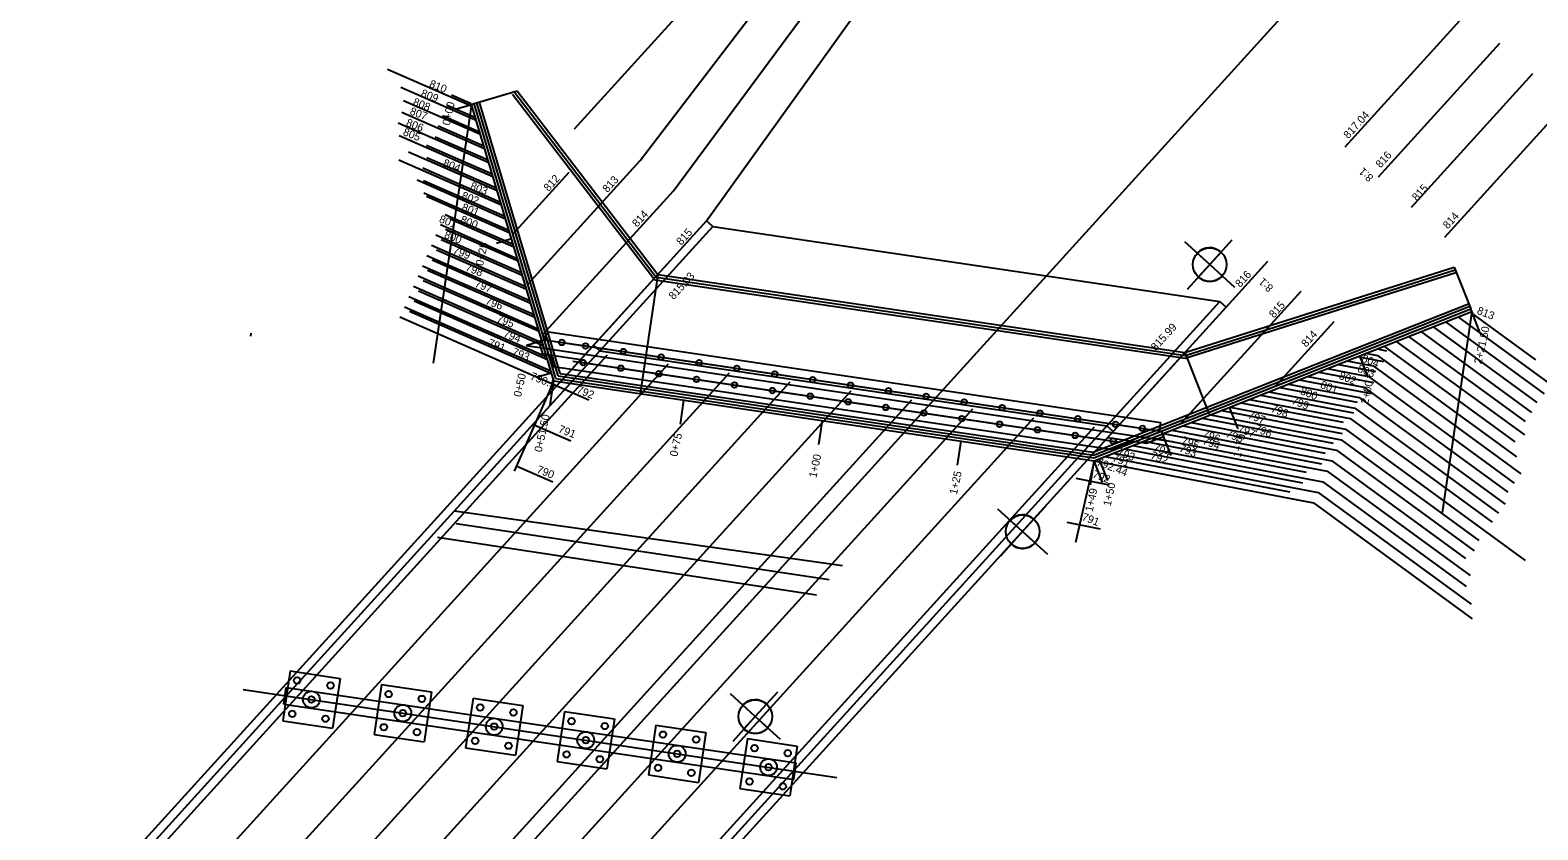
# Model space of a CAD drawing. Extents: x 1465887 to 1476191, y 569684 to 581027.
# Drawn here: x 1469566.9 to 1469836.1, y 574105.8 to 574248.6 of the extents above; entities that cross this region are included whole.
import ezdxf

# ---------------------------------------------------------------- set-up
doc = ezdxf.new("R2010")
doc.units = 0
for name, color, linetype in [('BR_P_Beam_Centerline', 7, 'Continuous'), ('BR_P_Brg_Centerline', 7, 'Continuous'), ('BR_P_Gen_Approach_Slab', 7, 'Continuous'), ('BR_P_Gen_Ground_Slope', 7, 'Continuous'), ('BR_P_Gen_Perforated_Pipe', 7, 'Continuous'), ('BR_P_Gen_Porous_Backfill', 7, 'Continuous'), ('BR_P_Gen_Profile_Grade', 7, 'Continuous'), ('BR_P_Gen_Slope_Protection', 7, 'Continuous'), ('BR_P_Rail_Object', 7, 'Continuous'), ('BR_P_Sub_Centerline', 7, 'Continuous'), ('BR_P_Sub_Deep_Centerline', 7, 'Continuous'), ('BR_P_Sub_Deep_Hidden', 7, 'Continuous'), ('BR_P_Sub_Foot_Hidden', 7, 'Continuous'), ('BR_P_Sub_Hidden', 7, 'Continuous'), ('BR_P_Sub_Object', 7, 'Continuous'), ('GT_Project_Soil_Boring', 7, 'Continuous'), ('PV_X_EOP', 7, 'Continuous'), ('PV_X_Shoulder', 7, 'Continuous'), ('SC_Scratch1', 7, 'Continuous'), ('UT_X_Water', 7, 'Continuous')]:
    doc.layers.add(name, color=color, linetype=linetype)

msp = doc.modelspace()

# ---------------------------------------------------------------- linework, layer by layer
at = {"layer": 'BR_P_Beam_Centerline'}
for p, q in [((1469558.94, 574068.28), (1469670.01, 574190.58)), ((1469569.81, 574066.67), (1469680.87, 574188.97)), ((1469580.67, 574065.06), (1469691.74, 574187.37)), ((1469591.54, 574063.45), (1469702.6, 574185.76)), ((1469602.4, 574061.85), (1469713.47, 574184.15)), ((1469613.27, 574060.24), (1469724.33, 574182.54)), ((1469624.13, 574058.63), (1469735.2, 574180.93)), ((1469635, 574057.02), (1469746.07, 574179.32)), ((1469645.86, 574055.41), (1469756.93, 574177.71))]:
    msp.add_line(p, q, dxfattribs=at)
at = {"layer": 'BR_P_Brg_Centerline'}
msp.add_line((1469655.47, 574192.23), (1469770.87, 574175.14), dxfattribs=at)
at = {"layer": 'BR_P_Gen_Approach_Slab'}
for p, q in [((1469688.79, 574213.5), (1469779.29, 574200.1)), ((1469668.62, 574191.29), (1469759.12, 574177.89))]:
    msp.add_line(p, q, dxfattribs=at)
at = {"layer": 'BR_P_Gen_Ground_Slope'}
for p, q in [((1469675.84, 574225.26), (1469758.84, 574334.16)), ((1469681.76, 574219.89), (1469763.29, 574330.13)), ((1469687.68, 574214.51), (1469767.73, 574326.09)), ((1469801.67, 574227.73), (1469823.35, 574251.6)), ((1469807.6, 574222.35), (1469829.27, 574246.22)), ((1469645.81, 574234.92), (1469630.69, 574241.55)), ((1469813.52, 574216.97), (1469835.19, 574240.84)), ((1469646.55, 574232.41), (1469633.12, 574238.3)), ((1469647.3, 574229.9), (1469633.58, 574235.92)), ((1469645.67, 574235.39), (1469642.15, 574236.93)), ((1469819.44, 574211.59), (1469841.12, 574235.46)), ((1469648.05, 574227.39), (1469633.26, 574233.87)), ((1469647.16, 574230.37), (1469640.55, 574233.27)), ((1469646.41, 574232.88), (1469641.35, 574235.1)), ((1469648.8, 574224.87), (1469632.59, 574231.98)), ((1469647.91, 574227.85), (1469639.74, 574231.44)), ((1469649.54, 574222.36), (1469632.79, 574229.71)), ((1469649.4, 574222.83), (1469637.7, 574227.96)), ((1469648.66, 574225.34), (1469639.23, 574229.48)), ((1469651.04, 574217.34), (1469632.73, 574225.37)), ((1469650.29, 574219.85), (1469634.49, 574226.78)), ((1469650.15, 574220.32), (1469637.71, 574225.78)), ((1469655.78, 574203.18), (1469675.84, 574225.26)), ((1469651.79, 574214.83), (1469636, 574221.75)), ((1469650.9, 574217.81), (1469637.04, 574223.89)), ((1469653.11, 574212.14), (1469663.14, 574223.19)), ((1469651.65, 574215.3), (1469637.15, 574221.65)), ((1469652.4, 574212.78), (1469637.18, 574219.46)), ((1469658.45, 574194.21), (1469681.76, 574219.89)), ((1469652.54, 574212.31), (1469637.66, 574218.84)), ((1469653.89, 574207.76), (1469640.17, 574213.78)), ((1469653.14, 574210.27), (1469640.98, 574215.61)), ((1469653.28, 574209.8), (1469641.89, 574214.8)), ((1469654.64, 574205.25), (1469639.37, 574211.94)), ((1469654.78, 574204.78), (1469640.29, 574211.14)), ((1469654.03, 574207.29), (1469641.09, 574212.97)), ((1469656.14, 574200.22), (1469637.76, 574208.28)), ((1469655.39, 574202.74), (1469638.57, 574210.11)), ((1469655.53, 574202.27), (1469639.48, 574209.3)), ((1469656.88, 574197.71), (1469636.96, 574206.45)), ((1469657.02, 574197.24), (1469637.88, 574205.64)), ((1469656.27, 574199.75), (1469638.68, 574207.47)), ((1469780.4, 574199.09), (1469787.86, 574207.31)), ((1469657.63, 574195.2), (1469636.16, 574204.62)), ((1469657.77, 574194.73), (1469637.07, 574203.81)), ((1469659.13, 574190.18), (1469634.55, 574200.95)), ((1469658.38, 574192.69), (1469635.35, 574202.79)), ((1469659.27, 574189.71), (1469635.47, 574200.15)), ((1469658.52, 574192.22), (1469636.27, 574201.98)), ((1469772.35, 574178.34), (1469793.78, 574201.93)), ((1469659.87, 574187.66), (1469633.75, 574199.12)), ((1469660.01, 574187.2), (1469634.66, 574198.31)), ((1469823.99, 574198.22), (1469835.63, 574189.71)), ((1469666.67, 574182.5), (1469632.94, 574197.29)), ((1469789.22, 574185), (1469799.7, 574196.55)), ((1469817.39, 574195.61), (1469835.89, 574182.09)), ((1469819.59, 574196.48), (1469837.16, 574183.64)), ((1469821.79, 574197.35), (1469838.65, 574185.03)), ((1469606.33, 574194.45), (1469606.25, 574193.95)), ((1469808.59, 574192.13), (1469831.92, 574175.08)), ((1469810.79, 574193), (1469833.66, 574176.29)), ((1469812.99, 574193.87), (1469833.79, 574178.67)), ((1469815.19, 574194.74), (1469834.93, 574180.31)), ((1469801.94, 574189.5), (1469806.64, 574188.6)), ((1469803.88, 574190.27), (1469808.48, 574189.39)), ((1469805.3, 574190.89), (1469807.46, 574190.48)), ((1469807.35, 574191.64), (1469809.02, 574191.32)), ((1469807.46, 574190.48), (1469832.24, 574172.37)), ((1469795, 574186.75), (1469805.01, 574184.84)), ((1469796.94, 574187.52), (1469806.7, 574185.65)), ((1469798.47, 574188.13), (1469805.83, 574186.72)), ((1469800.41, 574188.89), (1469807.07, 574187.62)), ((1469805.83, 574186.72), (1469831.85, 574167.7)), ((1469806.64, 574188.6), (1469833.03, 574169.32)), ((1469660.39, 574185.94), (1469653.32, 574169.83)), ((1469788.06, 574184.01), (1469803.37, 574181.08)), ((1469790, 574184.78), (1469803.78, 574182.14)), ((1469791.53, 574185.38), (1469804.19, 574182.96)), ((1469793.47, 574186.15), (1469806.32, 574183.69)), ((1469805.01, 574184.84), (1469830.67, 574166.09)), ((1469783.06, 574182.03), (1469801.28, 574178.54)), ((1469784.59, 574182.64), (1469802.56, 574179.2)), ((1469786.53, 574183.41), (1469803.16, 574180.22)), ((1469804.19, 574182.96), (1469830.24, 574163.93)), ((1469776.13, 574179.29), (1469799.55, 574174.8)), ((1469777.65, 574179.89), (1469800.92, 574175.44)), ((1469779.59, 574180.66), (1469801.13, 574176.54)), ((1469781.12, 574181.27), (1469801.74, 574177.32)), ((1469802.56, 574179.2), (1469827.88, 574160.7)), ((1469803.37, 574181.08), (1469829.06, 574162.31)), ((1469663.46, 574175.17), (1469656.92, 574178.04)), ((1469769.19, 574176.55), (1469797.45, 574171.13)), ((1469770.71, 574177.15), (1469799.29, 574171.68)), ((1469772.66, 574177.92), (1469798.07, 574173.05)), ((1469774.18, 574178.52), (1469800.11, 574173.56)), ((1469801.74, 574177.32), (1469833.79, 574153.9)), ((1469762.25, 574173.8), (1469794.03, 574167.72)), ((1469763.77, 574174.4), (1469797.65, 574167.92)), ((1469765.72, 574175.17), (1469794.71, 574169.62)), ((1469767.24, 574175.78), (1469798.47, 574169.8)), ((1469800.11, 574173.56), (1469824.68, 574155.61)), ((1469800.92, 574175.44), (1469825.52, 574157.47)), ((1469660.24, 574167.85), (1469653.71, 574170.71)), ((1469756.84, 574171.66), (1469753.52, 574157.08)), ((1469756.84, 574171.66), (1469796.02, 574164.16)), ((1469758.78, 574172.43), (1469791.77, 574166.11)), ((1469760.31, 574173.03), (1469796.84, 574166.04)), ((1469799.29, 574171.68), (1469823.16, 574154.24)), ((1469753.58, 574168.57), (1469759.51, 574167.38)), ((1469797.65, 574167.92), (1469823.24, 574149.22)), ((1469798.47, 574169.8), (1469823.96, 574151.18)), ((1469796.84, 574166.04), (1469824.13, 574146.1)), ((1469796.02, 574164.16), (1469824.34, 574143.47)), ((1469752, 574160.72), (1469757.94, 574159.53))]:
    msp.add_line(p, q, dxfattribs=at)
at = {"layer": 'BR_P_Gen_Perforated_Pipe'}
for p, q in [((1469661.16, 574186.84), (1469646.65, 574235.58)), ((1469661.55, 574187.28), (1469647.13, 574235.73)), ((1469653.05, 574237.12), (1469678.43, 574203.99)), ((1469653.44, 574237.42), (1469678.7, 574204.46)), ((1469773.09, 574190.48), (1469821.28, 574205.75)), ((1469678.43, 574203.99), (1469773.13, 574189.97)), ((1469678.7, 574204.46), (1469773.09, 574190.48)), ((1469773.13, 574189.97), (1469821.43, 574205.28)), ((1469756.66, 574173.2), (1469823.7, 574199.72)), ((1469756.72, 574172.69), (1469823.89, 574199.25)), ((1469661.16, 574186.84), (1469756.72, 574172.69)), ((1469661.55, 574187.28), (1469756.66, 574173.2))]:
    msp.add_line(p, q, dxfattribs=at)
at = {"layer": 'BR_P_Gen_Porous_Backfill'}
for p, q in [((1469646.17, 574235.44), (1469653.84, 574237.72)), ((1469653.84, 574237.72), (1469678.98, 574204.92)), ((1469773.04, 574191), (1469821.13, 574206.23)), ((1469821.13, 574206.23), (1469824.07, 574198.79)), ((1469678.98, 574204.92), (1469773.04, 574191))]:
    msp.add_line(p, q, dxfattribs=at)
at = {"layer": 'BR_P_Gen_Profile_Grade'}
msp.add_line((1469397.14, 573817.97), (1469976.08, 574455.48), dxfattribs=at)
at = {"layer": 'BR_P_Gen_Slope_Protection'}
for p, q in [((1469645.69, 574235.3), (1469646.17, 574235.44)), ((1469660.39, 574185.94), (1469645.69, 574235.3)), ((1469660.78, 574186.39), (1469646.17, 574235.44)), ((1469756.78, 574172.18), (1469824.07, 574198.79)), ((1469756.84, 574171.66), (1469824.26, 574198.32)), ((1469824.26, 574198.32), (1469824.07, 574198.79)), ((1469660.39, 574185.94), (1469756.84, 574171.66)), ((1469660.78, 574186.39), (1469756.78, 574172.18))]:
    msp.add_line(p, q, dxfattribs=at)
at = {"layer": 'BR_P_Rail_Object'}
for p, q in [((1469535.47, 574046.9), (1469687.68, 574214.51)), ((1469688.79, 574213.5), (1469687.68, 574214.51)), ((1469612.41, 574129.39), (1469688.79, 574213.5)), ((1469627.08, 574032.49), (1469779.29, 574200.1)), ((1469628.19, 574031.49), (1469780.4, 574199.09)), ((1469779.29, 574200.1), (1469780.4, 574199.09)), ((1469668.62, 574191.29), (1469667.51, 574192.3)), ((1469759.12, 574177.89), (1469760.23, 574176.89)), ((1469536.58, 574045.89), (1469612.41, 574129.39))]:
    msp.add_line(p, q, dxfattribs=at)
at = {"layer": 'BR_P_Sub_Centerline'}
msp.add_line((1469604.95, 574130.84), (1469710.92, 574115.15), dxfattribs=at)
at = {"layer": 'BR_P_Sub_Deep_Centerline'}
for p, q in [((1469660.62, 574192.98), (1469766.46, 574177.31)), ((1469663.77, 574189.48), (1469761.5, 574175.01))]:
    msp.add_line(p, q, dxfattribs=at)
at = {"layer": 'BR_P_Sub_Deep_Hidden'}
for centre, radius in [((1469661.84, 574192.8), 0.5), ((1469666.05, 574192.18), 0.5), ((1469665.61, 574189.21), 0.5), ((1469672.81, 574191.18), 0.5), ((1469679.57, 574190.18), 0.5), ((1469686.33, 574189.18), 0.5), ((1469672.37, 574188.21), 0.5), ((1469679.13, 574187.21), 0.5), ((1469685.89, 574186.21), 0.5), ((1469693.09, 574188.17), 0.5), ((1469699.85, 574187.17), 0.5), ((1469692.65, 574185.21), 0.5), ((1469699.41, 574184.21), 0.5), ((1469706.61, 574186.17), 0.5), ((1469713.37, 574185.17), 0.5), ((1469720.13, 574184.17), 0.5), ((1469706.17, 574183.21), 0.5), ((1469712.93, 574182.2), 0.5), ((1469719.69, 574181.2), 0.5), ((1469726.89, 574183.17), 0.5), ((1469733.65, 574182.17), 0.5), ((1469740.41, 574181.17), 0.5), ((1469726.45, 574180.2), 0.5), ((1469733.21, 574179.2), 0.5), ((1469739.97, 574178.2), 0.5), ((1469747.17, 574180.17), 0.5), ((1469753.92, 574179.17), 0.5), ((1469760.68, 574178.17), 0.5), ((1469746.73, 574177.2), 0.5), ((1469753.49, 574176.2), 0.5), ((1469765.47, 574177.46), 0.5), ((1469760.25, 574175.2), 0.5), ((1469614.6, 574132.45), 0.583), ((1469620.54, 574131.57), 0.583), ((1469630.92, 574130.03), 0.583), ((1469617.13, 574129.04), 0.583), ((1469636.86, 574129.15), 0.583), ((1469647.25, 574127.61), 0.583), ((1469613.72, 574126.51), 0.583), ((1469619.66, 574125.63), 0.583), ((1469633.45, 574126.62), 0.583), ((1469649.77, 574124.21), 0.583), ((1469653.18, 574126.73), 0.583), ((1469663.57, 574125.2), 0.583), ((1469669.5, 574124.32), 0.583), ((1469630.05, 574124.09), 0.583), ((1469635.98, 574123.21), 0.583), ((1469646.37, 574121.68), 0.583), ((1469666.1, 574121.79), 0.583), ((1469679.89, 574122.78), 0.583), ((1469685.83, 574121.9), 0.583), ((1469652.3, 574120.8), 0.583), ((1469662.69, 574119.26), 0.583), ((1469682.42, 574119.37), 0.583), ((1469696.21, 574120.36), 0.583), ((1469702.15, 574119.48), 0.583), ((1469668.62, 574118.38), 0.583), ((1469679.01, 574116.84), 0.583), ((1469698.74, 574116.96), 0.583), ((1469684.95, 574115.97), 0.583), ((1469695.33, 574114.43), 0.583), ((1469701.27, 574113.55), 0.583)]:
    msp.add_circle(centre, radius, dxfattribs=at)
at = {"layer": 'BR_P_Sub_Foot_Hidden'}
for p, q in [((1469658.72, 574193.86), (1469659.43, 574194.67)), ((1469658.91, 574193.23), (1469658.72, 574193.86)), ((1469659.43, 574194.67), (1469768.76, 574178.49)), ((1469660.33, 574188.48), (1469659.7, 574190.59)), ((1469660.33, 574188.48), (1469760.17, 574173.69)), ((1469768.54, 574177.01), (1469768.76, 574178.49)), ((1469760.17, 574173.69), (1469763.89, 574175.17)), ((1469613.34, 574134.15), (1469612.02, 574125.25)), ((1469613.34, 574134.15), (1469622.24, 574132.83)), ((1469622.24, 574132.83), (1469620.92, 574123.93)), ((1469629.66, 574131.73), (1469628.34, 574122.83)), ((1469629.66, 574131.73), (1469638.56, 574130.41)), ((1469638.56, 574130.41), (1469637.24, 574121.51)), ((1469645.98, 574129.32), (1469644.66, 574120.41)), ((1469645.98, 574129.32), (1469654.89, 574128)), ((1469654.89, 574128), (1469653.57, 574119.09)), ((1469612.02, 574125.25), (1469620.92, 574123.93)), ((1469662.3, 574126.9), (1469660.99, 574118)), ((1469662.3, 574126.9), (1469671.21, 574125.58)), ((1469671.21, 574125.58), (1469669.89, 574116.68)), ((1469628.34, 574122.83), (1469637.24, 574121.51)), ((1469678.63, 574124.48), (1469677.31, 574115.58)), ((1469678.63, 574124.48), (1469687.53, 574123.17)), ((1469687.53, 574123.17), (1469686.21, 574114.26)), ((1469644.66, 574120.41), (1469653.57, 574119.09)), ((1469694.95, 574122.07), (1469693.63, 574113.16)), ((1469694.95, 574122.07), (1469703.85, 574120.75)), ((1469703.85, 574120.75), (1469702.53, 574111.85)), ((1469660.99, 574118), (1469669.89, 574116.68)), ((1469677.31, 574115.58), (1469686.21, 574114.26)), ((1469693.63, 574113.16), (1469702.53, 574111.85))]:
    msp.add_line(p, q, dxfattribs=at)
at = {"layer": 'BR_P_Sub_Hidden'}
for p, q in [((1469665.22, 574189.77), (1469664.82, 574189.33)), ((1469667.24, 574192), (1469761.31, 574178.07)), ((1469664.82, 574189.33), (1469758.88, 574175.4)), ((1469759.29, 574175.85), (1469758.88, 574175.4)), ((1469612.21, 574128.25), (1469612.65, 574131.22)), ((1469612.65, 574131.22), (1469703.66, 574117.74)), ((1469612.21, 574128.25), (1469703.22, 574114.78)), ((1469703.22, 574114.78), (1469703.66, 574117.74))]:
    msp.add_line(p, q, dxfattribs=at)
for centre in [(1469617.13, 574129.04), (1469633.45, 574126.62), (1469649.77, 574124.21), (1469666.1, 574121.79), (1469682.42, 574119.37), (1469698.74, 574116.96)]:
    msp.add_circle(centre, 1.5, dxfattribs=at)
at = {"layer": 'BR_P_Sub_Object'}
for p, q in [((1469658.73, 574193.26), (1469657.77, 574192.98)), ((1469658.43, 574190.78), (1469657.77, 574192.98)), ((1469658.73, 574193.26), (1469667.24, 574192)), ((1469658.43, 574190.78), (1469665.22, 574189.77)), ((1469761.31, 574178.07), (1469768.87, 574176.96)), ((1469766.19, 574174.82), (1469769.23, 574176.03)), ((1469768.87, 574176.96), (1469769.23, 574176.03)), ((1469759.29, 574175.85), (1469766.19, 574174.82))]:
    msp.add_line(p, q, dxfattribs=at)
at = {"layer": 'GT_Project_Soil_Boring'}
for p, q in [((1469777.49, 574206.71), (1469781.52, 574211.15)), ((1469777.49, 574206.71), (1469773.05, 574210.74)), ((1469777.49, 574206.71), (1469775.27, 574208.72)), ((1469779.51, 574208.93), (1469777.49, 574206.71)), ((1469777.49, 574206.71), (1469773.46, 574202.26)), ((1469775.47, 574204.49), (1469777.49, 574206.71)), ((1469777.49, 574206.71), (1469781.93, 574202.67)), ((1469777.49, 574206.71), (1469779.71, 574204.69)), ((1469744.08, 574159.03), (1469739.64, 574163.06)), ((1469744.08, 574159.03), (1469748.12, 574163.47)), ((1469744.08, 574159.03), (1469741.86, 574161.04)), ((1469746.1, 574161.25), (1469744.08, 574159.03)), ((1469744.08, 574159.03), (1469740.05, 574154.58)), ((1469742.07, 574156.8), (1469744.08, 574159.03)), ((1469744.08, 574159.03), (1469748.52, 574154.99)), ((1469744.08, 574159.03), (1469746.3, 574157.01)), ((1469696.37, 574126.01), (1469700.4, 574130.45)), ((1469696.37, 574126.01), (1469691.93, 574130.05)), ((1469696.37, 574126.01), (1469694.15, 574128.03)), ((1469698.39, 574128.23), (1469696.37, 574126.01)), ((1469696.37, 574126.01), (1469692.34, 574121.57)), ((1469694.35, 574123.79), (1469696.37, 574126.01)), ((1469696.37, 574126.01), (1469700.81, 574121.98)), ((1469696.37, 574126.01), (1469698.59, 574124))]:
    msp.add_line(p, q, dxfattribs=at)
for centre in [(1469777.49, 574206.71), (1469744.08, 574159.03), (1469696.37, 574126.01)]:
    msp.add_circle(centre, 3, dxfattribs=at)
for centre, start, end in [((1469777.49, 574206.71), 47.7565, 137.7565), ((1469777.49, 574206.71), 227.7565, 317.7565), ((1469744.08, 574159.03), 47.7565, 137.7565), ((1469744.08, 574159.03), 227.7565, 317.7565), ((1469696.37, 574126.01), 47.7565, 137.7565), ((1469696.37, 574126.01), 227.7565, 317.7565)]:
    msp.add_arc(centre, 3, start, end, dxfattribs=at)
at = {"layer": 'PV_X_EOP'}
msp.add_line((1469639.62, 574158.03), (1469707.32, 574147.72), dxfattribs=at)
at = {"layer": 'PV_X_Shoulder'}
msp.add_line((1469642.67, 574162.73), (1469711.95, 574152.96), dxfattribs=at)
at = {"layer": 'SC_Scratch1'}
for p, q in [((1469664.1, 574230.94), (1469770.2, 574347.77)), ((1469645.69, 574235.3), (1469638.86, 574189.13)), ((1469643.02, 574234.5), (1469645.69, 574235.3)), ((1469650.15, 574210.54), (1469652.83, 574211.34)), ((1469661.58, 574185.76), (1469678.98, 574204.92)), ((1469678.98, 574204.92), (1469675.83, 574183.65)), ((1469824.26, 574198.32), (1469818.95, 574162.47)), ((1469825.79, 574194.45), (1469824.26, 574198.32)), ((1469655.57, 574192.32), (1469658.25, 574193.12)), ((1469755.65, 574171.84), (1469773.04, 574191)), ((1469773.04, 574191), (1469777.46, 574179.82)), ((1469805.79, 574186.54), (1469804.26, 574190.42)), ((1469657.28, 574186.58), (1469659.96, 574187.38)), ((1469659.75, 574181.67), (1469660.39, 574185.94)), ((1469683, 574178.22), (1469683.63, 574182.5)), ((1469707.73, 574174.56), (1469708.36, 574178.84)), ((1469782.55, 574177.35), (1469781.01, 574181.22)), ((1469770.58, 574172.62), (1469769.05, 574176.49)), ((1469732.46, 574170.9), (1469733.1, 574175.18)), ((1469756.2, 574167.39), (1469756.84, 574171.66)), ((1469758.37, 574167.79), (1469756.84, 574171.66)), ((1469759.3, 574168.15), (1469757.77, 574172.03))]:
    msp.add_line(p, q, dxfattribs=at)
at = {"layer": 'UT_X_Water'}
msp.add_line((1469642.97, 574160.5), (1469709.54, 574150.45), dxfattribs=at)

# ---------------------------------------------------------------- texts
at = {"layer": 'BR_P_Gen_Ground_Slope'}
for s, rotation, p in [('809', 338.5632, (1469636.55, 574236.78)), ('810', 338.5632, (1469638.06, 574238.45)), ('808', 338.5632, (1469635.13, 574235.22)), ('806', 338.5632, (1469633.91, 574231.51)), ('807', 338.5632, (1469634.58, 574233.57)), ('817.04', 47.7564, (1469802.24, 574229.07)), ('805', 338.5632, (1469633.36, 574229.86)), ('804', 338.5632, (1469640.5, 574224.32)), ('816', 47.7564, (1469807.98, 574223.85)), ('812', 47.7564, (1469659.48, 574219.66)), ('813', 47.7564, (1469669.97, 574219.46)), ('8:1', 137.7564, (1469806.82, 574222.38)), ('802', 338.5632, (1469643.8, 574218.49)), ('803', 338.5632, (1469645.36, 574220.22)), ('815', 47.7564, (1469814.48, 574217.95)), ('801', 338.5632, (1469643.84, 574216.43)), ('814', 47.7564, (1469675.26, 574213.29)), ('801', 338.5632, (1469639.81, 574214.31)), ('800', 338.5632, (1469643.6, 574214.21)), ('814', 47.7564, (1469819.98, 574212.96)), ('800', 338.5632, (1469640.71, 574211.51)), ('815', 47.7564, (1469683.15, 574210.05)), ('799', 338.5632, (1469642.27, 574208.74)), ('798', 338.5632, (1469644.5, 574205.67)), ('816', 47.7564, (1469782.92, 574202.53)), ('797', 338.5632, (1469646.17, 574202.79)), ('815.03', 47.7564, (1469681.8, 574200.33)), ('8:1', 137.7564, (1469788.95, 574202.7)), ('796', 338.5632, (1469648.07, 574199.71)), ('815', 47.7564, (1469788.95, 574197.06)), ('795', 338.5632, (1469650.08, 574196.52)), ('813', 338.5632, (1469825.07, 574197.96)), ('794', 338.5632, (1469651.29, 574193.86)), ('815.99', 47.7564, (1469767.86, 574191.21)), ('814', 47.7564, (1469794.7, 574191.84)), ('791', 338.5632, (1469648.53, 574192.21)), ('793', 338.5632, (1469652.83, 574190.61)), ('804', 338.5632, (1469804.48, 574189.44)), ('790.5', 338.5632, (1469656.07, 574186.24)), ('802', 338.5632, (1469800.42, 574186.35)), ('803', 338.5632, (1469803.74, 574187.63)), ('792', 338.5632, (1469664.37, 574183.83)), ('800', 338.5632, (1469793.52, 574183.61)), ('801', 338.5632, (1469797.11, 574184.73)), ('798', 338.5632, (1469788.3, 574180.49)), ('799', 338.5632, (1469791.96, 574181.89)), ('797', 338.5632, (1469784.18, 574179.33)), ('791', 338.5632, (1469661.08, 574176.82)), ('795', 338.5632, (1469772.34, 574174.81)), ('796', 338.5632, (1469776.1, 574175.98)), ('794', 338.5632, (1469776.1, 574174.73)), ('795', 338.5632, (1469780.24, 574176)), ('797', 338.5632, (1469782.39, 574176.9)), ('796', 338.5632, (1469785.36, 574176.93)), ('793', 338.5632, (1469760.88, 574172.75)), ('792', 338.5632, (1469766.78, 574172.1)), ('794', 338.5632, (1469767.29, 574173.5)), ('793', 338.5632, (1469771.93, 574173.4)), ('790', 338.5632, (1469657.23, 574169.59)), ('792.44', 338.5632, (1469757.17, 574170.93)), ('791', 338.5632, (1469759.98, 574171.67)), ('792', 338.5632, (1469756.46, 574168.76)), ('791', 338.5632, (1469754.55, 574161.14))]:
    msp.add_text(s, height=1.4, rotation=rotation, dxfattribs=at).set_placement(p)
at = {"layer": 'SC_Scratch1'}
for s, p in [('0+00', (1469641.83, 574231.47)), ('0+25', (1469647.77, 574206.39)), ('2+21.50', (1469826.01, 574188.85)), ('0+50', (1469654.55, 574182.98)), ('2+00', (1469805.75, 574181.7)), ('0+51.50', (1469658.25, 574173.13)), ('0+75', (1469682.43, 574172.33)), ('1+75', (1469782.96, 574172.19)), ('1+00', (1469707.27, 574168.56)), ('1+25', (1469732.35, 574165.55)), ('1+49', (1469756.57, 574162.48)), ('1+50', (1469759.79, 574163.49))]:
    msp.add_text(s, height=1.4, rotation=77.7564, dxfattribs=at).set_placement(p)

doc.saveas('drawing.dxf')
